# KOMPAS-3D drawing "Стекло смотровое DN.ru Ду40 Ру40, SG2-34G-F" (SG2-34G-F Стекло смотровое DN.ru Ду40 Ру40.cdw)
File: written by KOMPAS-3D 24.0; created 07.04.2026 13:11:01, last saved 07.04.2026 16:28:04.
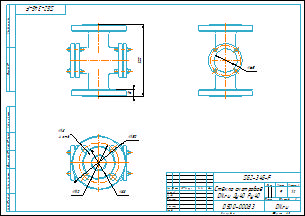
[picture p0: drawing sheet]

Document properties: Автор: Main; Форматы листов документа: A3; Полное имя файла: SG2-34G-F Стекло смотровое DN.ru Ду40 Ру40.m3d; Масса: 9; Наименование: Стекло смотровое DN.ru Ду40 Ру40; Количество листов документа: 1; Примечание: D500-00083

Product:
- Part/product: Стекло смотровое DN.ru Ду40 Ру40  | designation SG2-34G-F
    Масса: 9
    Раздел спецификации: Прочие изделия
    Примечание: D500-00083

Views: Вид 1, Снизу, Проекционный вид 2
Referenced files in D:\DN.ru Аутсерс\Стекло смотровое DN.ru\Стекло смотровое DN.ru SG2-34G-F тип В ГОСТ 21836-2021 Ду100 Ру16, углеродистая сталь, фланцевое\: SG2-34G-F тип В Стекло смотровое DN.ru Ду100 Ру16.m3d, SG2-34G-F тип ВСтекло смотровое DN.ru Ду100 Ру16.cdw
Referenced files in D:\DN.ru Аутсерс\Стекло смотровое DN.ru\SG2-34G-F Стекло смотровое DN.ru Ду40 Ру40\: SG2-34G-F Стекло смотровое DN.ru Ду40 Ру40.m3d
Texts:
  SG2-34G-F
  Стекло смотровое
  DN.ru Ду40 Ру40
  Стекло смотровое DN.ru Ду40 Ру40
  SG2-34G-F Стекло смотровое DN.ru Ду40 Ру40
Dimensions and other numbers on the sheet: 0; 3; 2; 4; 200; 18; 150; 4 отв.; 88; 110; 1:2; 1; 9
